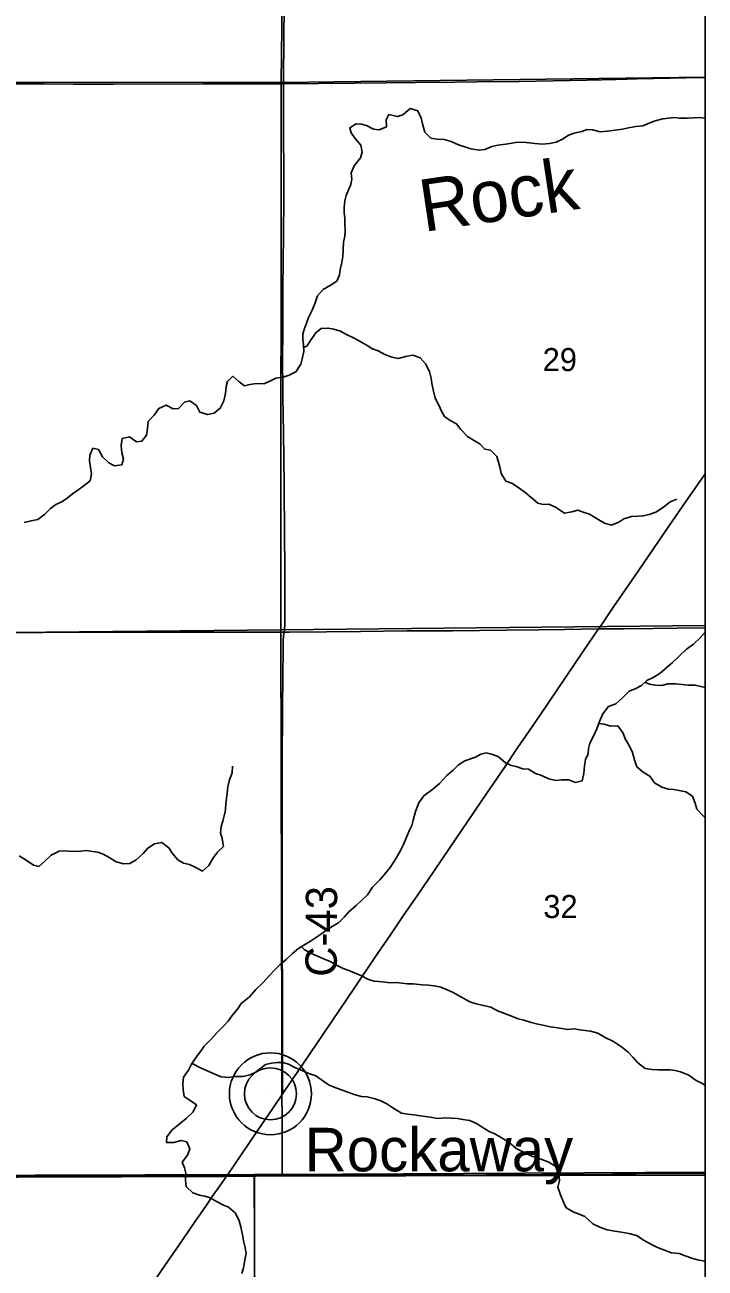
# Model space of a CAD drawing. Extents: x 0 to 34, y 0 to 22.
# Drawn here: x 8.783 to 9.4, y 17.325 to 18.454 of the extents above; entities that cross this region are included whole.
import ezdxf

# ---------------------------------------------------------------- set-up
doc = ezdxf.new("R2010")
doc.units = 0
for name, color, linetype in [('GM_X_County', 7, 'Continuous'), ('GM_X_County_Road', 7, 'Continuous'), ('GM_X_County_Road_Text', 7, 'Continuous'), ('GM_X_Minor_River', 7, 'Continuous'), ('GM_X_Minor_River_Text', 7, 'Continuous'), ('GM_X_Section', 7, 'Continuous'), ('GM_X_Section_Text', 7, 'Continuous'), ('GM_X_State_Route', 7, 'Continuous'), ('GM_X_Township', 7, 'Continuous'), ('GM_X_Township_Road', 7, 'Continuous'), ('GM_X_Unincorporated', 7, 'Continuous'), ('GM_X_Unincorporated_Location', 7, 'Continuous'), ('GM_X_Unincorporated_Text', 7, 'Continuous'), ('GM_X_US_Route', 7, 'Continuous'), ('SH_Data', 7, 'Continuous')]:
    doc.layers.add(name, color=color, linetype=linetype)

msp = doc.modelspace()

# ---------------------------------------------------------------- linework, layer by layer
at = {"layer": 'GM_X_County'}
msp.add_lwpolyline([(9.4, 14.3965), (9.4, 20.9), (2.6, 20.9), (2.6, 14.4092)], dxfattribs=at)
at = {"layer": 'GM_X_County_Road'}
for points in [[(9.0174, 18.4004), (9.0178, 18.445), (9.0183, 18.4888), (9.0186, 18.5248), (9.0188, 18.5484), (9.019, 18.5935), (9.0196, 18.633), (9.0204, 18.6992), (9.0212, 18.7517), (9.0216, 18.7803), (9.0218, 18.8051), (9.022, 18.8281), (9.0222, 18.8502), (9.0225, 18.8701), (9.0226, 18.8874), (9.0227, 18.902)], [(9.0179, 17.9024), (9.0183, 17.9049), (9.0185, 17.9066), (9.0186, 17.9077), (9.0186, 17.9109), (9.0188, 17.9171), (9.0188, 17.9466), (9.0187, 17.9616), (9.0185, 17.9898), (9.018, 18.0349), (9.0176, 18.0607), (9.0173, 18.0833), (9.0167, 18.1159), (9.0166, 18.1572), (9.0167, 18.1681), (9.0169, 18.1929), (9.0169, 18.2181), (9.017, 18.2352), (9.0174, 18.2663), (9.0176, 18.2927), (9.0177, 18.3104), (9.0174, 18.3642), (9.0173, 18.399), (9.0174, 18.4004)], [(9.0174, 17.4842), (9.0169, 17.486), (9.0165, 17.4884), (9.0166, 17.4995), (9.0166, 17.512), (9.0166, 17.53), (9.0165, 17.553), (9.0165, 17.5847), (9.0163, 17.608), (9.0162, 17.6278), (9.0163, 17.6629), (9.0163, 17.6896), (9.0162, 17.7), (9.0162, 17.7075), (9.0163, 17.7308), (9.0162, 17.7485), (9.0163, 17.7789), (9.0163, 17.7998), (9.0165, 17.8168), (9.0166, 17.8364), (9.0167, 17.8597), (9.017, 17.8892), (9.0172, 17.8957), (9.0174, 17.8978), (9.0174, 17.8993), (9.0176, 17.9007), (9.0179, 17.9022), (9.0179, 17.9024)], [(8.991, 17.3145), (8.9911, 17.3655), (8.9911, 17.3757), (8.9912, 17.3829), (8.9912, 17.3857), (8.9912, 17.3919), (8.9912, 17.4058), (8.9912, 17.4087)]]:
    msp.add_lwpolyline(points, dxfattribs=at)
at = {"layer": 'GM_X_Minor_River'}
for points in [[(9.0044, 18.13), (9.0105, 18.133), (9.017, 18.1339), (9.0227, 18.1358), (9.0287, 18.1388), (9.0331, 18.1456), (9.0345, 18.1505), (9.0358, 18.1573), (9.0357, 18.1632), (9.0349, 18.1684), (9.0351, 18.1733), (9.0365, 18.178), (9.0384, 18.1831), (9.0401, 18.1881), (9.0436, 18.1947), (9.0463, 18.2015), (9.0484, 18.2078), (9.0535, 18.2136), (9.0608, 18.2178), (9.0657, 18.221), (9.0682, 18.2269), (9.069, 18.2316), (9.0703, 18.2379), (9.0713, 18.2434), (9.0717, 18.2494), (9.0719, 18.2566), (9.0731, 18.2621), (9.0733, 18.2671), (9.0732, 18.2733), (9.073, 18.2783), (9.0724, 18.2834), (9.0725, 18.2881), (9.073, 18.2942), (9.0744, 18.299), (9.0765, 18.3039), (9.0784, 18.3088), (9.0794, 18.3137), (9.0787, 18.3196), (9.0815, 18.3257), (9.0874, 18.3332), (9.0888, 18.3382), (9.0875, 18.3446), (9.0826, 18.3507), (9.0788, 18.3557), (9.0775, 18.3604), (9.0834, 18.364), (9.0881, 18.3636), (9.0929, 18.3626), (9.0991, 18.359), (9.1041, 18.3586), (9.1109, 18.3612), (9.1107, 18.3675), (9.113, 18.3724), (9.1208, 18.3705), (9.1258, 18.3722), (9.1324, 18.378), (9.1393, 18.3759), (9.1423, 18.3691), (9.1438, 18.3628), (9.1456, 18.3565), (9.1511, 18.351), (9.157, 18.35), (9.1632, 18.3498), (9.1695, 18.3479), (9.1761, 18.345), (9.1828, 18.3429), (9.1875, 18.3414), (9.1949, 18.3402), (9.2, 18.3407), (9.2065, 18.3434), (9.2118, 18.3445), (9.2169, 18.3452), (9.2232, 18.3461), (9.228, 18.3469), (9.2348, 18.3474), (9.2405, 18.3468), (9.2456, 18.3461), (9.2524, 18.3456), (9.2589, 18.3462), (9.265, 18.3473), (9.2712, 18.3503), (9.276, 18.3537), (9.2813, 18.3554), (9.288, 18.3569), (9.2929, 18.3588), (9.2977, 18.3585), (9.3049, 18.3568), (9.3111, 18.3572), (9.3183, 18.3583), (9.325, 18.359), (9.3305, 18.3603), (9.3372, 18.3616), (9.3436, 18.3621), (9.3499, 18.365), (9.3546, 18.3667), (9.3615, 18.3685)], [(9.3615, 18.3685), (9.3721, 18.3696), (9.3769, 18.3692), (9.3837, 18.369), (9.3896, 18.3694), (9.3945, 18.3697), (9.3996, 18.3691), (9.4, 18.3691)], [(9.0357, 18.1609), (9.0385, 18.1621), (9.0427, 18.1681), (9.0467, 18.1742), (9.0515, 18.178), (9.0578, 18.1785), (9.0631, 18.1775), (9.0691, 18.1756), (9.0746, 18.1726), (9.0811, 18.1695), (9.0875, 18.166), (9.0934, 18.1626), (9.0983, 18.1597), (9.1032, 18.1578), (9.1095, 18.1544), (9.1157, 18.1521), (9.1218, 18.1509), (9.1281, 18.1528), (9.1349, 18.1539), (9.1413, 18.1516), (9.1464, 18.1459), (9.1498, 18.139), (9.1513, 18.1329), (9.1521, 18.1282), (9.1534, 18.1212), (9.155, 18.1149), (9.1584, 18.1084), (9.1609, 18.1031), (9.1635, 18.0982), (9.1686, 18.0947), (9.1743, 18.0915), (9.1785, 18.0863), (9.1845, 18.0799), (9.1906, 18.076), (9.1955, 18.0734), (9.2002, 18.0684), (9.2053, 18.0676), (9.211, 18.0619), (9.2136, 18.0524), (9.2149, 18.0463), (9.2193, 18.0395), (9.2251, 18.0372), (9.2314, 18.033), (9.2363, 18.0295), (9.2423, 18.0246), (9.2482, 18.0194), (9.2531, 18.0183), (9.2583, 18.0186), (9.2641, 18.0158), (9.2725, 18.0104), (9.2791, 18.0117), (9.2844, 18.013), (9.2903, 18.0111), (9.2951, 18.0095), (9.3021, 18.0053), (9.3087, 18.0013), (9.3151, 17.9994), (9.3216, 18.0022), (9.3263, 18.0054), (9.3332, 18.0073), (9.3395, 18.0076), (9.3442, 18.008), (9.3491, 18.0093), (9.3554, 18.0114), (9.3623, 18.0159), (9.3682, 18.0206), (9.3744, 18.0231)], [(8.7822, 18.002), (8.7885, 18.0033), (8.7945, 18.0046), (8.8006, 18.0092), (8.8061, 18.0147), (8.8109, 18.0184), (8.8162, 18.0207), (8.8212, 18.0241), (8.8259, 18.0279), (8.8307, 18.0313), (8.8366, 18.0354), (8.8421, 18.0399), (8.8431, 18.046), (8.8422, 18.0519), (8.8414, 18.058), (8.8417, 18.0631), (8.8445, 18.0693), (8.8495, 18.0682), (8.8532, 18.0615), (8.8591, 18.056), (8.8642, 18.0535), (8.8707, 18.0544), (8.8724, 18.0594), (8.8709, 18.0652), (8.8702, 18.0719), (8.8711, 18.0783), (8.8776, 18.0796), (8.8842, 18.0752), (8.889, 18.0758), (8.893, 18.0811), (8.894, 18.0872), (8.8947, 18.0936), (8.9001, 18.0995), (8.9043, 18.1055), (8.9109, 18.1085), (8.9174, 18.1051), (8.9223, 18.1054), (8.9275, 18.1113), (8.9324, 18.1124), (8.9385, 18.1082), (8.9415, 18.102), (8.9485, 18.1), (8.9544, 18.1011), (8.9601, 18.1057), (8.9633, 18.1125), (8.9649, 18.1191), (8.9655, 18.1254), (8.9666, 18.1301), (8.9716, 18.1348), (8.9773, 18.1297), (8.9822, 18.1259), (8.9869, 18.1272), (8.9926, 18.1281), (8.9997, 18.1279), (9.0044, 18.13)], [(9.0981, 17.6709), (9.1048, 17.6775), (9.1103, 17.6837), (9.1143, 17.6886), (9.1197, 17.697), (9.1235, 17.704), (9.1262, 17.7095), (9.1285, 17.7146), (9.1314, 17.7218), (9.1339, 17.7267), (9.135, 17.7316), (9.1373, 17.7396), (9.1402, 17.7472), (9.1448, 17.7538), (9.1528, 17.7598), (9.1589, 17.7649), (9.1657, 17.7721), (9.1713, 17.777), (9.1762, 17.7817), (9.1821, 17.7855), (9.1916, 17.7889), (9.1966, 17.7915), (9.2013, 17.7926), (9.2061, 17.7915), (9.2123, 17.7894), (9.2189, 17.7837), (9.2239, 17.7812), (9.2286, 17.7802), (9.2347, 17.7783), (9.2398, 17.7779), (9.246, 17.774), (9.251, 17.7725), (9.2582, 17.7691), (9.2646, 17.7677), (9.2697, 17.7683), (9.2764, 17.7682), (9.2824, 17.7659), (9.2885, 17.7674), (9.2899, 17.7739), (9.2905, 17.7811), (9.2916, 17.7866), (9.2938, 17.7917), (9.2943, 17.7966), (9.2953, 17.8015), (9.2984, 17.8072), (9.3018, 17.8146), (9.3043, 17.8211), (9.3072, 17.8281), (9.3123, 17.8347), (9.319, 17.8373), (9.3247, 17.8424), (9.3312, 17.8488), (9.3371, 17.8511), (9.3422, 17.8539), (9.347, 17.8583), (9.3535, 17.8616), (9.3592, 17.865), (9.3639, 17.869), (9.3704, 17.8749), (9.3763, 17.8801), (9.383, 17.887), (9.3894, 17.8913), (9.3955, 17.8973), (9.4, 17.9023)], [(9.3454, 17.8568), (9.3496, 17.855), (9.3549, 17.8542), (9.3608, 17.854), (9.3663, 17.8553), (9.373, 17.8555), (9.3792, 17.8547), (9.3845, 17.8541), (9.391, 17.8541), (9.3961, 17.8531), (9.4, 17.8522)], [(9.3037, 17.8194), (9.3083, 17.8188), (9.3145, 17.817), (9.3208, 17.8174), (9.3255, 17.8105), (9.3276, 17.8054), (9.331, 17.7993), (9.334, 17.793), (9.3359, 17.7864), (9.3381, 17.7801), (9.3438, 17.7751), (9.3498, 17.7715), (9.3542, 17.7656), (9.3606, 17.7616), (9.3669, 17.7597), (9.3716, 17.7593), (9.3779, 17.7583), (9.3826, 17.7573), (9.3887, 17.7533), (9.3911, 17.7469), (9.3926, 17.7417), (9.3981, 17.7356), (9.4, 17.7336)], [(8.7775, 17.6992), (8.7841, 17.6954), (8.7907, 17.6906), (8.7955, 17.6896), (8.8006, 17.694), (8.8067, 17.6998), (8.8138, 17.7034), (8.8187, 17.7036), (8.8259, 17.7031), (8.8337, 17.7033), (8.8386, 17.7039), (8.8441, 17.7031), (8.8489, 17.7025), (8.8538, 17.7006), (8.8599, 17.6973), (8.8657, 17.6937), (8.8725, 17.6919), (8.8779, 17.6923), (8.8839, 17.6955), (8.8902, 17.7012), (8.8942, 17.7063), (8.9003, 17.7102), (8.9072, 17.7112), (8.9134, 17.7066), (8.9166, 17.7014), (8.9215, 17.6957), (8.9266, 17.6925), (8.9323, 17.6913), (8.9374, 17.689), (8.9439, 17.6854), (8.9496, 17.6905), (8.9534, 17.6969), (8.9576, 17.7026), (8.963, 17.7077), (8.9617, 17.7149), (8.9604, 17.7202), (8.9609, 17.7259), (8.9625, 17.7308), (8.9636, 17.7356), (8.9648, 17.7409), (8.9652, 17.7466), (8.9656, 17.7513), (8.9662, 17.7561), (8.9668, 17.7618), (8.9685, 17.7682), (8.9708, 17.7746), (8.9712, 17.7807)], [(8.9795, 17.3199), (8.9811, 17.325), (8.9824, 17.3321), (8.9836, 17.3383), (8.9825, 17.3448), (8.9812, 17.3495), (8.9802, 17.355), (8.9786, 17.3624), (8.9771, 17.3678), (8.9739, 17.3746), (8.9674, 17.3801), (8.9623, 17.3824), (8.9574, 17.3851), (8.951, 17.3886), (8.946, 17.3901), (8.9413, 17.3909), (8.9352, 17.3932), (8.9292, 17.3989), (8.9285, 17.4048), (8.9289, 17.411), (8.9275, 17.4158), (8.9255, 17.4209), (8.9304, 17.4275), (8.9324, 17.4332), (8.9297, 17.4395), (8.9246, 17.4407), (8.918, 17.4388), (8.9113, 17.4388), (8.9115, 17.4439), (8.9165, 17.4504), (8.9224, 17.4553), (8.9291, 17.4606), (8.9355, 17.4666), (8.9384, 17.473), (8.9327, 17.4771), (8.9274, 17.4807), (8.9265, 17.4871), (8.926, 17.4919), (8.9268, 17.4981), (8.9312, 17.5046), (8.934, 17.5099), (8.9382, 17.5163), (8.942, 17.5214), (8.9455, 17.5263), (8.9518, 17.5328), (8.9575, 17.5392), (8.9628, 17.5443), (8.9672, 17.5492), (8.9708, 17.5543), (8.9756, 17.56), (8.9791, 17.5651), (8.9865, 17.5711), (8.9922, 17.5778), (8.9987, 17.584), (9.0046, 17.5904), (9.0092, 17.5955), (9.0141, 17.6001), (9.0198, 17.605), (9.0256, 17.6106), (9.0311, 17.615), (9.036, 17.6182), (9.0419, 17.6216), (9.0492, 17.6267), (9.0543, 17.6303), (9.061, 17.6346), (9.0672, 17.6384), (9.0726, 17.6435), (9.0766, 17.6484), (9.0834, 17.654), (9.0884, 17.6588), (9.0937, 17.6639), (9.0981, 17.6709)], [(9.0339, 17.6168), (9.0362, 17.614), (9.0428, 17.6104), (9.0483, 17.6081), (9.0532, 17.606), (9.0597, 17.6031), (9.0667, 17.5993), (9.0716, 17.597), (9.0767, 17.5951), (9.0877, 17.5905), (9.0945, 17.587), (9.0998, 17.5855), (9.1073, 17.5849), (9.1143, 17.5839), (9.1198, 17.5841), (9.13, 17.5829), (9.135, 17.583), (9.1433, 17.5822), (9.1488, 17.5818), (9.1545, 17.5811), (9.1602, 17.5799), (9.1653, 17.5778), (9.1715, 17.5751), (9.1782, 17.5711), (9.1865, 17.5667), (9.1922, 17.5648), (9.199, 17.5634), (9.2057, 17.5619), (9.2117, 17.5584), (9.2166, 17.5565), (9.2237, 17.5538), (9.2303, 17.5513), (9.2354, 17.55), (9.2422, 17.5479), (9.2483, 17.5463), (9.2544, 17.545), (9.2595, 17.5438), (9.2642, 17.5432), (9.2699, 17.5424), (9.275, 17.5415), (9.2813, 17.5422), (9.2862, 17.5412), (9.2912, 17.5406), (9.2959, 17.54), (9.3027, 17.5381), (9.3092, 17.5341), (9.3169, 17.5305), (9.3241, 17.5257), (9.3302, 17.5209), (9.3347, 17.5161), (9.3391, 17.5112), (9.3457, 17.506), (9.3521, 17.5053), (9.3578, 17.505), (9.3633, 17.505), (9.3681, 17.5048), (9.3728, 17.5044), (9.3777, 17.5031), (9.3853, 17.5), (9.3919, 17.4952), (9.3969, 17.4929), (9.4, 17.4905)], [(8.9345, 17.5106), (8.942, 17.5066), (8.9552, 17.5009), (8.9609, 17.4986), (8.9674, 17.498), (8.974, 17.4987), (8.9807, 17.4989), (8.9869, 17.5004), (8.9917, 17.5024), (8.9965, 17.5062), (9.0012, 17.5096), (9.0067, 17.5109), (9.0117, 17.5115), (9.0168, 17.5114), (9.0221, 17.5099), (9.0283, 17.5066), (9.035, 17.5038), (9.0405, 17.5016), (9.0469, 17.4993), (9.0541, 17.4942), (9.059, 17.4908), (9.0657, 17.4883), (9.0706, 17.4865), (9.0757, 17.4846), (9.0825, 17.4821), (9.0882, 17.4806), (9.0933, 17.4804), (9.1005, 17.4784), (9.1064, 17.4765), (9.1113, 17.474), (9.1168, 17.4702), (9.1246, 17.4656), (9.1303, 17.4645), (9.1358, 17.4639), (9.1418, 17.4631), (9.1504, 17.4619), (9.1574, 17.4607), (9.1637, 17.4613), (9.1695, 17.4611), (9.1752, 17.4607), (9.1802, 17.4599), (9.1864, 17.4587), (9.1932, 17.4558), (9.1987, 17.4522), (9.2046, 17.4486), (9.2093, 17.4468), (9.2158, 17.4428), (9.222, 17.4392), (9.2286, 17.4333), (9.2357, 17.4297), (9.2427, 17.4266), (9.2502, 17.4241), (9.2582, 17.421), (9.2654, 17.4166), (9.2673, 17.4109), (9.2678, 17.4045), (9.2665, 17.3984), (9.2689, 17.3914), (9.2715, 17.3847), (9.2738, 17.3796), (9.281, 17.3756), (9.2857, 17.3738), (9.291, 17.3717), (9.2982, 17.3651), (9.305, 17.3618), (9.3111, 17.3597), (9.3181, 17.3583), (9.324, 17.3575), (9.3308, 17.3562), (9.3378, 17.3543), (9.3448, 17.3499), (9.3513, 17.3462), (9.3569, 17.3436), (9.363, 17.3411), (9.3694, 17.3386), (9.3765, 17.3382), (9.3818, 17.336), (9.388, 17.3337), (9.393, 17.3322), (9.3994, 17.3312), (9.4, 17.3312)]]:
    msp.add_lwpolyline(points, dxfattribs=at)
at = {"layer": 'GM_X_Section'}
for p, q in [((9.4, 18.4063), (9.4, 18.9096)), ((9.4, 17.9085), (9.4, 18.4063)), ((9.4, 17.4118), (9.4, 17.9085)), ((9.4, 16.9096), (9.4, 17.4118))]:
    msp.add_line(p, q, dxfattribs=at)
for points in [[(8.4981, 18.9029), (9.0213, 18.9032), (9.0152, 18.4014), (8.4994, 18.4021), (8.4999, 18.4122)], [(8.4994, 18.4021), (9.0152, 18.4014), (9.0151, 17.9046), (8.4969, 17.8994), (8.4969, 17.9091)], [(8.4969, 17.8994), (9.0151, 17.9046), (9.0162, 17.4099), (8.9908, 17.4098), (8.4938, 17.4083)], [(8.4938, 17.4083), (8.9908, 17.4098), (8.9931, 16.916), (8.4891, 16.9146)]]:
    msp.add_lwpolyline(points, close=True, dxfattribs=at)
for points in [[(9.4, 18.9096), (9.0213, 18.9032), (9.0152, 18.4014), (9.4, 18.4063)], [(9.4, 18.4063), (9.0152, 18.4014), (9.0151, 17.9046), (9.4, 17.9085)], [(9.4, 17.9085), (9.0151, 17.9046), (9.0162, 17.4099), (9.4, 17.4118)], [(9.4, 17.4118), (9.0162, 17.4099), (8.9908, 17.4098), (8.9931, 16.916), (9.4, 16.9096)]]:
    msp.add_lwpolyline(points, dxfattribs=at)
at = {"layer": 'GM_X_State_Route'}
for points in [[(9.0233, 17.4929), (9.0299, 17.5025), (9.0419, 17.5203), (9.0534, 17.5373), (9.0686, 17.5596), (9.0818, 17.5792), (9.1004, 17.6068), (9.1146, 17.6276), (9.1261, 17.6446), (9.1393, 17.6638), (9.1541, 17.6857), (9.168, 17.7063), (9.2019, 17.7562), (9.2179, 17.7795), (9.2299, 17.7972), (9.24, 17.8121), (9.2505, 17.8276), (9.2734, 17.8613), (9.2832, 17.876), (9.2941, 17.8919), (9.3033, 17.9053), (9.3047, 17.9073), (9.3169, 17.9252), (9.3392, 17.9578), (9.3626, 17.9919), (9.3799, 18.017), (9.4, 18.0461)], [(8.9659, 17.4087), (8.9659, 17.4087), (8.9668, 17.4099), (8.9783, 17.4267), (8.9866, 17.4388), (8.9982, 17.4557), (9.0069, 17.4686), (9.0174, 17.4842), (9.018, 17.4851), (9.0233, 17.4929)], [(8.9013, 17.3147), (8.9099, 17.3272), (8.9201, 17.3421), (8.926, 17.3508), (8.9319, 17.3593), (8.9369, 17.3667), (8.942, 17.3742), (8.9475, 17.3821), (8.9528, 17.3898), (8.9596, 17.3994), (8.9659, 17.4087)]]:
    msp.add_lwpolyline(points, dxfattribs=at)
at = {"layer": 'GM_X_Township'}
for p, q in [((9.4, 17.4092), (9.4, 20.4572)), ((9.4, 14.3965), (9.4, 17.4092))]:
    msp.add_line(p, q, dxfattribs=at)
for points in [[(9.4, 20.4572), (9.0515, 20.4584), (9.0372, 20.4584), (8.5011, 20.4527), (8.493, 20.1675), (8.4861, 19.9159), (8.486, 19.9121), (8.4932, 19.4121), (8.4993, 18.91), (8.4999, 18.4019), (8.4971, 17.9043), (8.4927, 17.4064), (8.965, 17.4081), (8.9926, 17.4083), (9.4, 17.4092)], [(9.4, 17.4092), (8.9926, 17.4083), (8.965, 17.4081), (8.4927, 17.4064), (8.489, 16.9129), (8.4875, 16.7165), (8.4852, 16.414), (8.4805, 15.9065), (8.4802, 15.8707), (8.4804, 15.8413), (8.4727, 15.4034), (8.4648, 14.9001), (8.4648, 14.8948), (8.4627, 14.3996), (8.961, 14.3984), (8.9649, 14.3985), (9.4, 14.3965)]]:
    msp.add_lwpolyline(points, dxfattribs=at)
at = {"layer": 'GM_X_Township_Road'}
for points in [[(9.0174, 18.4004), (9.0492, 18.4006), (9.0821, 18.4009), (9.1104, 18.4012), (9.1371, 18.4015), (9.1729, 18.4018), (9.1931, 18.4022), (9.2313, 18.4025), (9.2931, 18.4035), (9.3192, 18.4043), (9.3385, 18.4048), (9.3826, 18.4058), (9.4, 18.4062)], [(8.7571, 18.4004), (8.8003, 18.4003), (8.827, 18.4001), (8.8633, 18.4001), (8.9445, 18.4002), (8.9783, 18.4002), (9.0091, 18.4003), (9.0174, 18.4004)], [(8.7479, 17.9016), (8.7991, 17.9021), (8.8467, 17.9023), (8.9004, 17.9022), (8.9349, 17.9023), (8.9632, 17.9023), (8.9896, 17.9024), (9.0179, 17.9024)], [(9.0179, 17.9024), (9.0229, 17.9024), (9.0564, 17.9027), (9.0872, 17.903), (9.1294, 17.9034), (9.1708, 17.9036), (9.2199, 17.9042), (9.2488, 17.9046), (9.2724, 17.9048), (9.3033, 17.9053)], [(9.3033, 17.9053), (9.3075, 17.9053), (9.3265, 17.9054), (9.3526, 17.9057), (9.3743, 17.9059), (9.4, 17.9062)]]:
    msp.add_lwpolyline(points, dxfattribs=at)
at = {"layer": 'GM_X_Unincorporated'}
for radius in [0.0372, 0.0236]:
    msp.add_circle((9.0056, 17.4831), radius, dxfattribs=at)
at = {"layer": 'GM_X_Unincorporated_Location'}
msp.add_line((9.0056, 17.4831), (9.0056, 17.4831), dxfattribs=at)
at = {"layer": 'GM_X_US_Route'}
for points in [[(8.9659, 17.4087), (8.9912, 17.4087), (9.0146, 17.4088), (9.0372, 17.4089), (9.0596, 17.4088), (9.0957, 17.4092), (9.1162, 17.4091), (9.1457, 17.4092), (9.169, 17.4092), (9.2013, 17.4094), (9.2517, 17.4097), (9.2728, 17.4097), (9.2943, 17.4099), (9.3374, 17.4104), (9.3779, 17.4106), (9.4, 17.4108)], [(8.7703, 17.4086), (8.7943, 17.4086), (8.825, 17.4086), (8.8632, 17.4086), (8.8772, 17.4086), (8.8893, 17.4087), (8.9033, 17.4087), (8.9226, 17.4087), (8.9605, 17.4087), (8.9659, 17.4087)]]:
    msp.add_lwpolyline(points, dxfattribs=at)
at = {"layer": 'SH_Data'}
msp.add_line((9.4, 20.9), (9.4, 14.1), dxfattribs=at)

# ---------------------------------------------------------------- texts
at = {"layer": 'GM_X_County_Road_Text'}
msp.add_text('C-43', height=0.02841, rotation=89.6588, dxfattribs=at).set_placement((9.0657, 17.5893))
at = {"layer": 'GM_X_Minor_River_Text'}
msp.add_text('Rock', height=0.04737, rotation=8.4808, dxfattribs=at).set_placement((9.1446, 18.2657))
at = {"layer": 'GM_X_Section_Text'}
for s, p in [('29', (9.2526, 18.1394)), ('32', (9.2532, 17.6427))]:
    msp.add_text(s, height=0.02093, rotation=0, dxfattribs=at).set_placement(p)
at = {"layer": 'GM_X_Unincorporated_Text'}
msp.add_text('Rockaway', height=0.03949, rotation=0, dxfattribs=at).set_placement((9.0367, 17.4127))

doc.saveas('drawing.dxf')
